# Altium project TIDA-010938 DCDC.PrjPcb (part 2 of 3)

## Sheet TIDA-010938 bidirectional DC-DC_Interleaved1.SchDoc
size 558 x 431 mm; Date: Not shown in title block; ApprovedBy: Not shown in title block; CheckedBy: Not shown in title block; Author: Not shown in title block; CompanyName: Not shown in title block; Engineer: Not shown in title block; Organization: Not shown in title block; Address1: Not shown in title block; Address2: Not shown in title block; Address3: Not shown in title block; Address4: Not shown in title block; DocumentNumber: 1; Revision: Use project parameter SCH_Rev; SheetNumber: 5; SheetTotal: 9; PageSetup: Record=PageOptions¦CenterHorizontal=True¦CenterVertical=True¦PrintScale=1.00¦XCorrection=1.00¦YCorrection=1.00¦PrintKind=0¦BorderSize=5000000¦LeftOffset=0¦BottomOffset=0¦Orientation=2¦PaperLength=1000¦PaperWidth=1000¦Scale=100¦PaperSource=15¦PrintQuality=600¦MediaType=1¦DitherType=10¦PaperKind=Letter¦PrintScaleMode=1
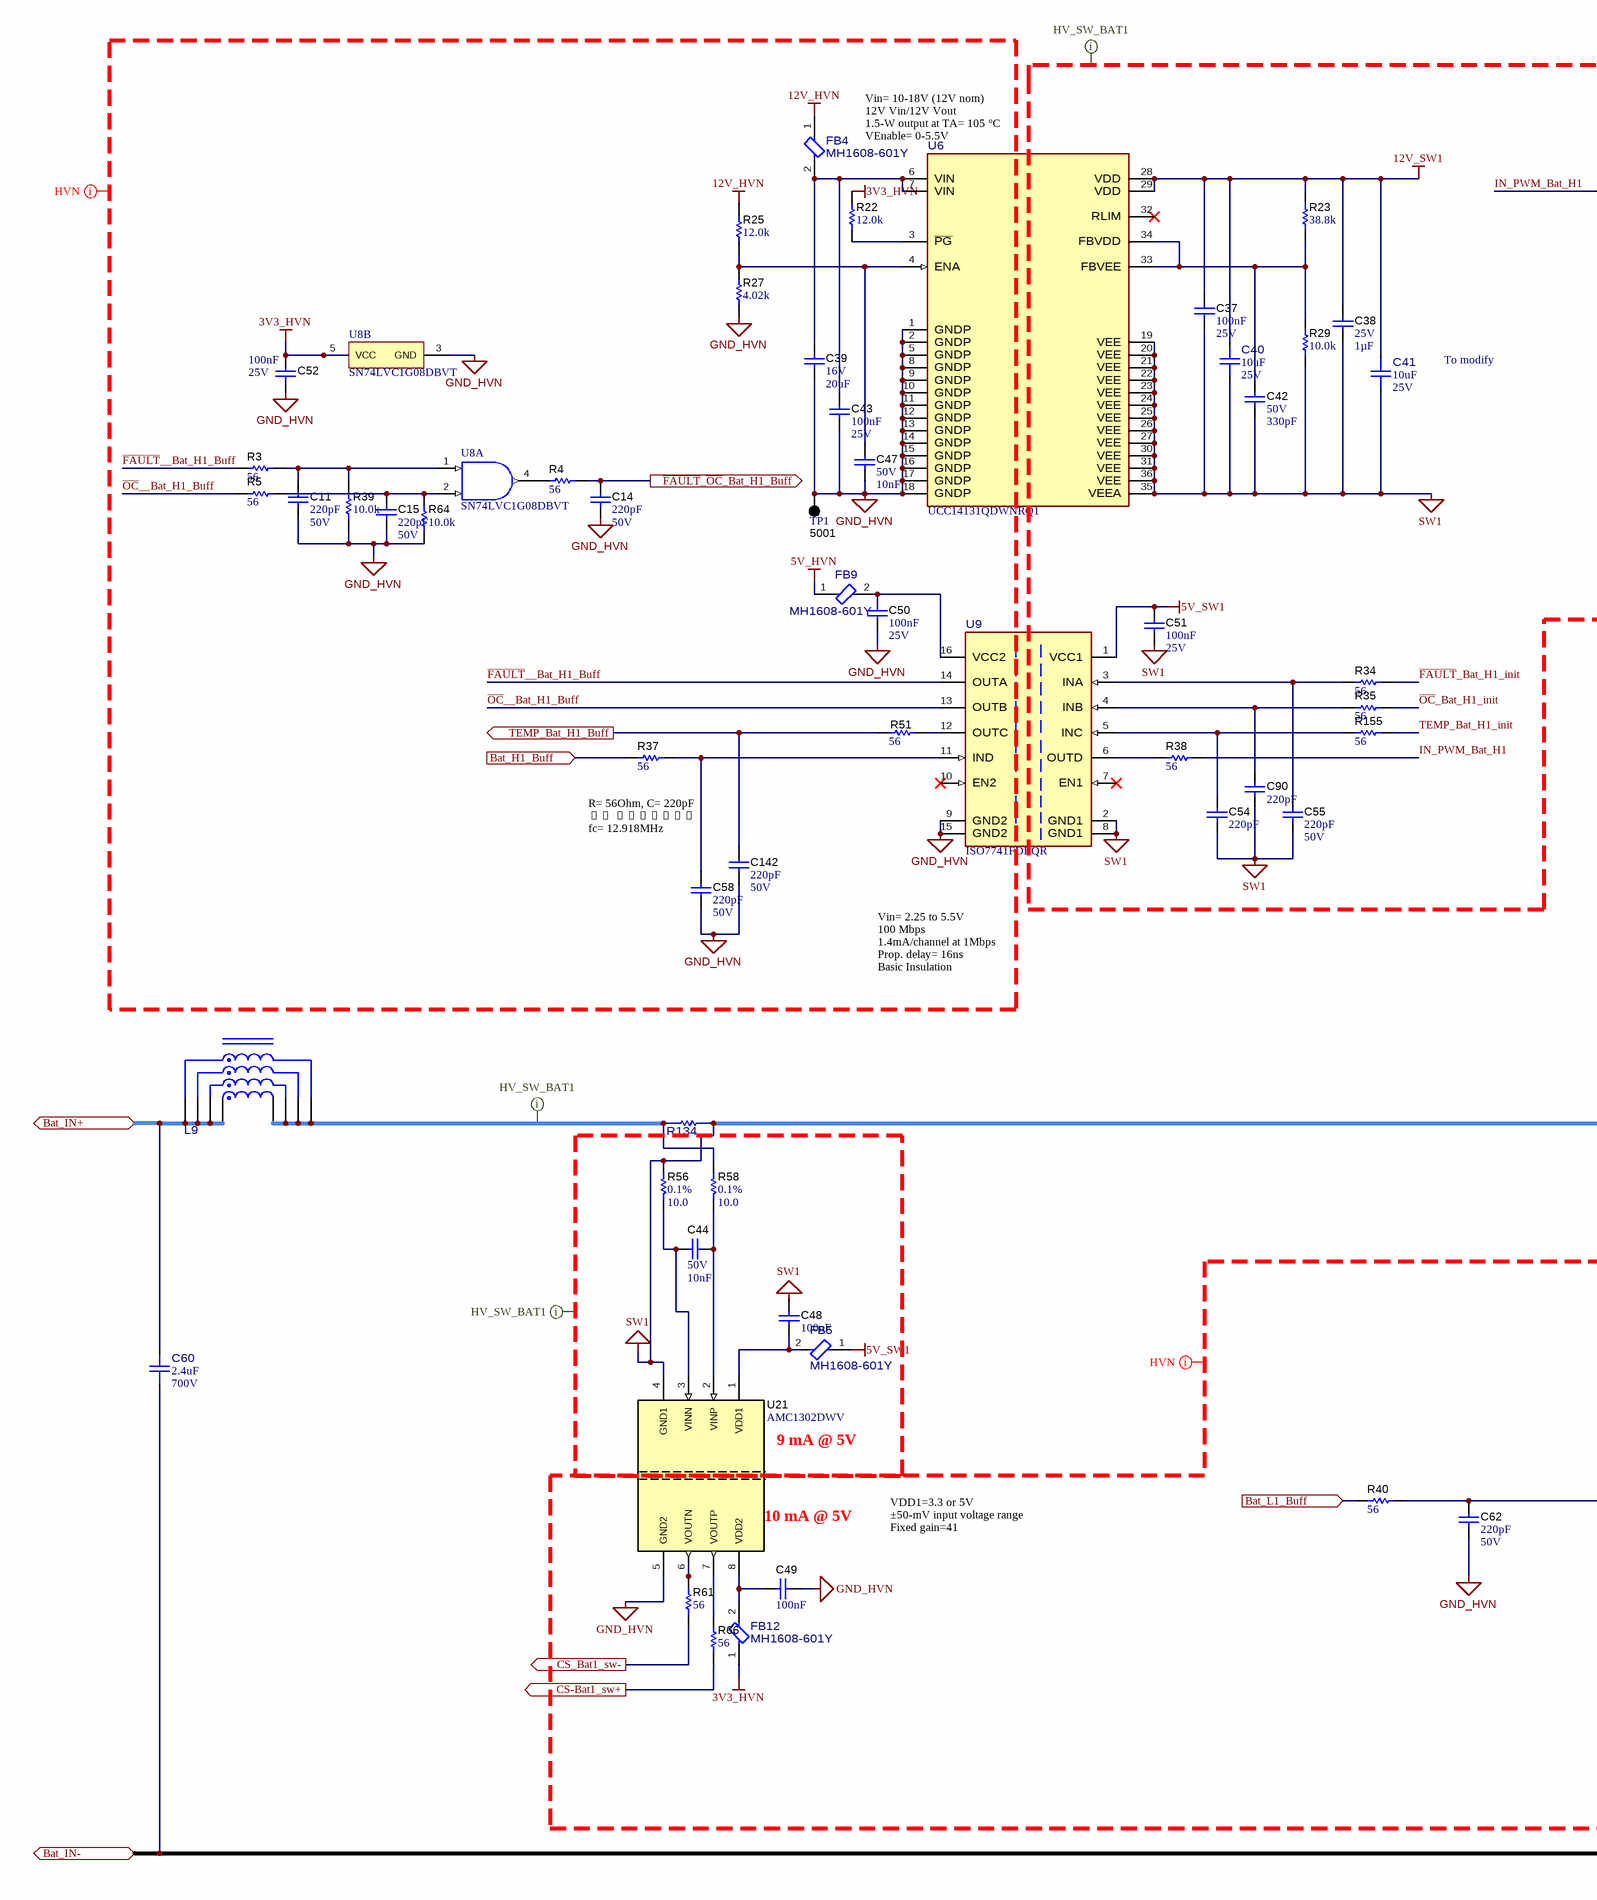
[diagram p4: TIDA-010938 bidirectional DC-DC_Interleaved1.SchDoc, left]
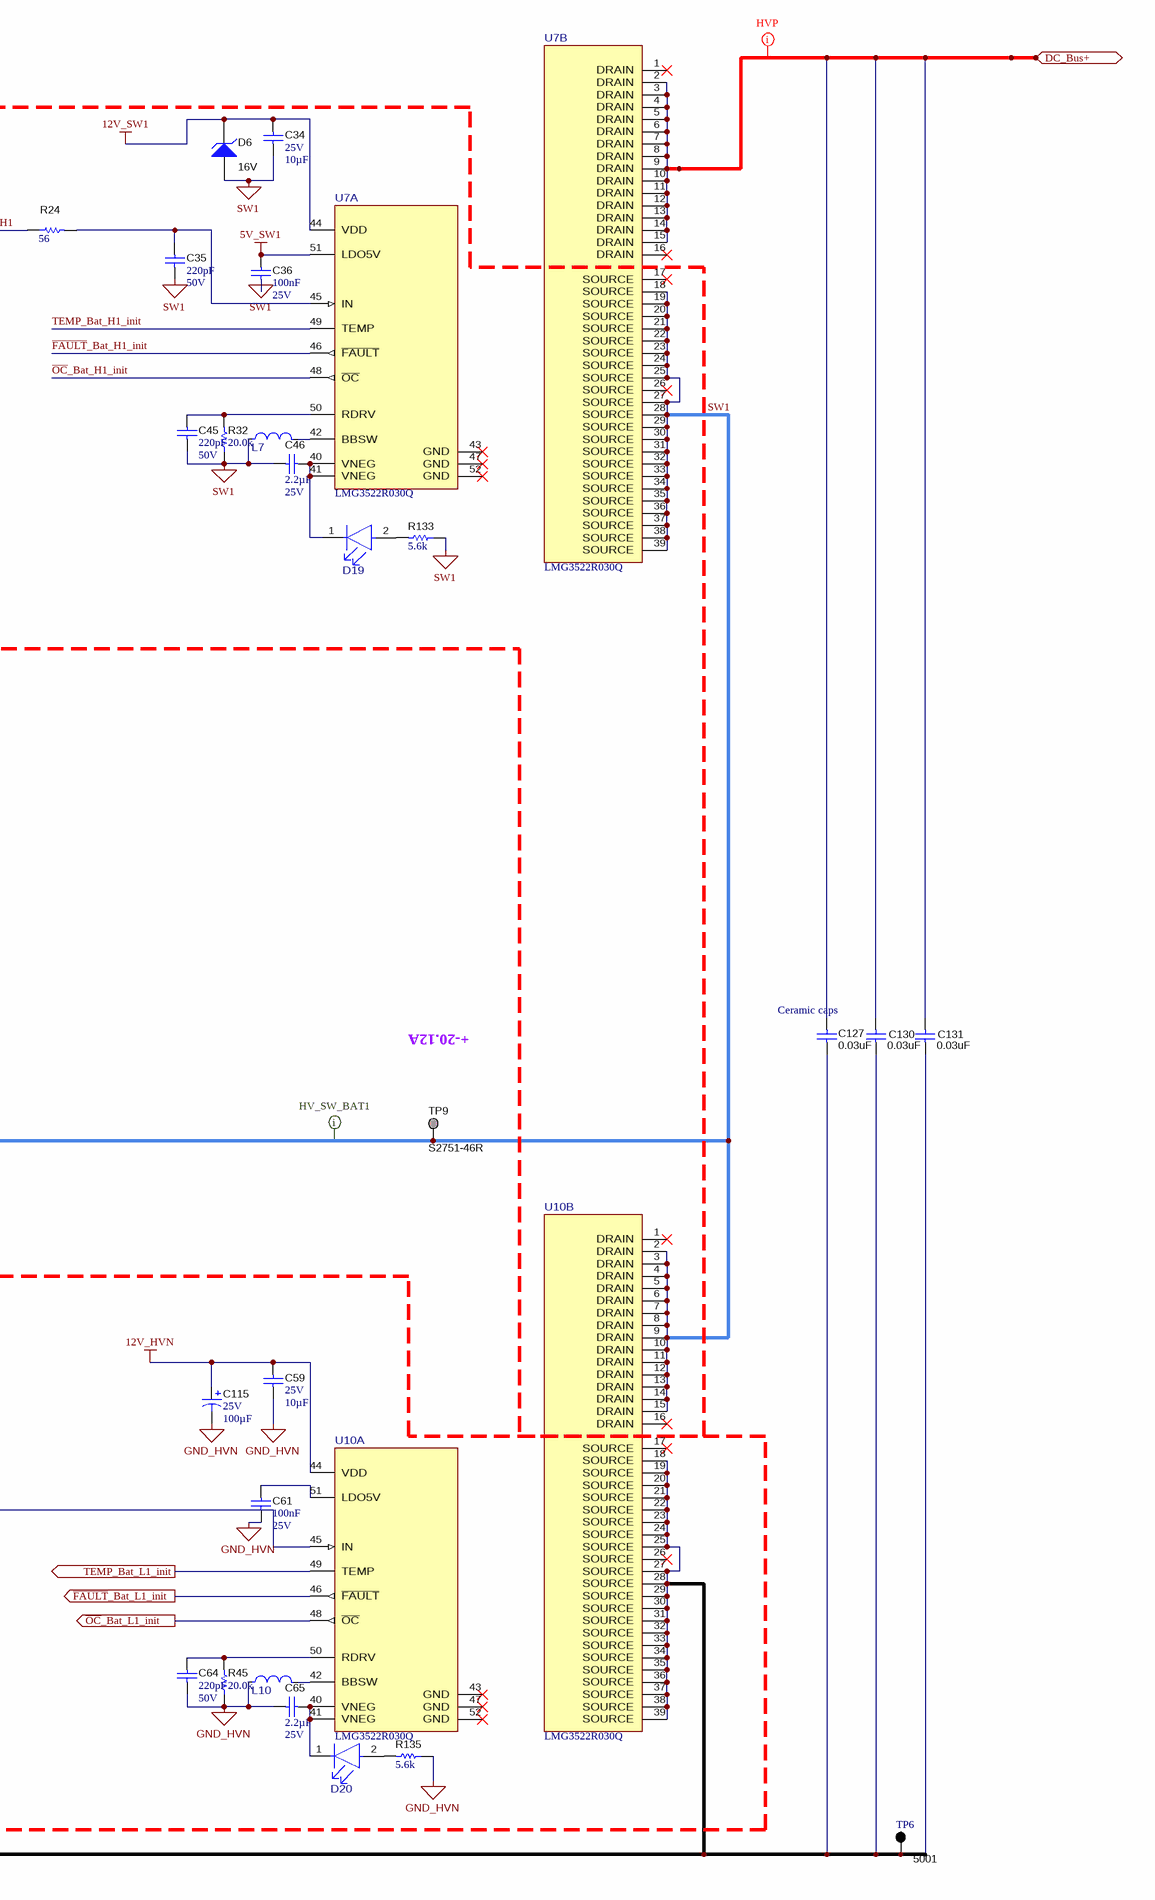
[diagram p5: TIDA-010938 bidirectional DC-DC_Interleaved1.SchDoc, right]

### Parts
C11  Cap_F: 220pF  VDC_V: 50V  [0603]  (hidden comment: GRM188R71H221KA01D)
C14  Cap_F: 220pF  VDC_V: 50V  [0603]  (hidden comment: GRM188R71H221KA01D)
C15  Cap_F: 220pF  VDC_V: 50V  [0603]  (hidden comment: GRM188R71H221KA01D)
C34  VDC_V: 25V  ValueDisplayed: 10µF  [1206_180]  (hidden comment: TMK316AB7106KLHT)
C35  Cap_F: 220pF  VDC_V: 50V  [0603]  (hidden comment: GRM188R71H221KA01D)
C36  Cap_F: 100nF  VDC_V: 25V  [0603]  (hidden comment: 06033C104JAT2A)
C37  Cap_F: 100nF  VDC_V: 25V  [0603]  (hidden comment: 06033C104JAT2A)
C38  VDC_V: 25V  ValueDisplayed: 1µF  [0603]  (hidden comment: TMK107BJ105KA-T)
C39  VDC_V: 16V  ValueDisplayed: 20uF  [0704]  (hidden comment: GRMJN7R61C206ME05)
C40  ValueDisplayed: 10uF  VDC_V: 25V  [FP-ZRB18AR61E106ME01L_0603-MFG]  (hidden comment: ZRB18AR61E106ME01L)
C41  ValueDisplayed: 10uF  VDC_V: 25V  [FP-ZRB18AR61E106ME01L_0603-MFG]  (hidden comment: ZRB18AR61E106ME01L)
C42  VDC_V: 50V  ValueDisplayed: 330pF  [0603]  (hidden comment: GRM1885C1H331JA01D)
C43  Cap_F: 100nF  VDC_V: 25V  [0603]  (hidden comment: 06033C104JAT2A)
C44  VDC_V: 50V  Cap_F: 10nF  [0603]  (hidden comment: 885012206089)
C45  Cap_F: 220pF  VDC_V: 50V  [0603]  (hidden comment: GRM188R71H221KA01D)
C46  Cap_F: 2.2µF  VDC_V: 25V  [0805_HV]  (hidden comment: CGA4J3X7R1E225K125AB)
C47  VDC_V: 50V  Cap_F: 10nF  [0603]  (hidden comment: 885012206089)
C48  Cap_F: 100nF  [0603]  (hidden comment: 06033C104JAT2A)
C49  Cap_F: 100nF  [0603]  (hidden comment: 06033C104JAT2A)
C50  Cap_F: 100nF  VDC_V: 25V  [0603]  (hidden comment: 06033C104JAT2A)
C51  Cap_F: 100nF  VDC_V: 25V  [0603]  (hidden comment: 06033C104JAT2A)
C52  Cap_F: 100nF  VDC_V: 25V  [0603]  (hidden comment: 06033C104JAT2A)
C54  Cap_F: 220pF  [0603]  (hidden comment: GRM188R71H221KA01D)
C55  Cap_F: 220pF  VDC_V: 50V  [0603]  (hidden comment: GRM188R71H221KA01D)
C58  Cap_F: 220pF  VDC_V: 50V  [0603]  (hidden comment: GRM188R71H221KA01D)
C59  VDC_V: 25V  ValueDisplayed: 10µF  [1206_180]  (hidden comment: TMK316AB7106KLHT)
C60  ValueDisplayed: 2.4uF  VDC_V: 700V  [FP-C4AUJBU4240M1WJ_RADIAL-MFG]  (hidden comment: C4AUJBU4240M1WJ)
C61  Cap_F: 100nF  VDC_V: 25V  [0603]  (hidden comment: 06033C104JAT2A)
C62  Cap_F: 220pF  VDC_V: 50V  [0603]  (hidden comment: GRM188R71H221KA01D)
C64  Cap_F: 220pF  VDC_V: 50V  [0603]  (hidden comment: GRM188R71H221KA01D)
C65  Cap_F: 2.2µF  VDC_V: 25V  [0805_HV]  (hidden comment: CGA4J3X7R1E225K125AB)
C90  Cap_F: 220pF  [0603]  (hidden comment: GRM188R71H221KA01D)
C115  VDC_V: 25V  ValueDisplayed: 100µF  [UWT_630x770]  (hidden comment: UWT1E101MCL1GS)
C127  ValueDisplayed: 0.03uF  [1812_254]  (hidden comment: C1812C303KDGLCAUTO)
C130  ValueDisplayed: 0.03uF  [1812_254]  (hidden comment: C1812C303KDGLCAUTO)
C131  ValueDisplayed: 0.03uF  [1812_254]  (hidden comment: C1812C303KDGLCAUTO)
C142  Cap_F: 220pF  VDC_V: 50V  [0603]  (hidden comment: GRM188R71H221KA01D)
D6  value 16V  [SOD-123]  (hidden comment: BZT52C16-7-F)
D19  KG DELLS1.22-JGKH-24  [FP-KG DELLS1.22-JGKH-24_0603-MFG]  (value not drawn)
D20  KG DELLS1.22-JGKH-24  [FP-KG DELLS1.22-JGKH-24_0603-MFG]  (value not drawn)
FB4  MH1608-601Y  [FP-MH1608-601Y_0603-MFG]
FB5  MH1608-601Y  [FP-MH1608-601Y_0603-MFG]
FB9  MH1608-601Y  [FP-MH1608-601Y_0603-MFG]
FB12  MH1608-601Y  [FP-MH1608-601Y_0603-MFG]
L7  SDEM20161T-4R7MS  [FP-SDEM20161T-4R7MS_SMD2-MFG]  (value not drawn)
L9  145452  [FP-145452_PTH_INDUCTOR_38MM5_60MM0-MFG]  (value not drawn)
L10  SDEM20161T-4R7MS  [FP-SDEM20161T-4R7MS_SMD2-MFG]  (value not drawn)
R3  ValueDisplayed: 56  [0603]  (hidden comment: RG1608P-560-B-T5)
R4  ValueDisplayed: 56  [0603]  (hidden comment: RG1608P-560-B-T5)
R5  ValueDisplayed: 56  [0603]  (hidden comment: RG1608P-560-B-T5)
R22  ValueDisplayed: 12.0k  [0603]  (hidden comment: ERJ-3EKF1202V)
R23  ValueDisplayed: 38.8k  [0603]  (hidden comment: RT0603DRE0738K8L)
R24  ValueDisplayed: 56  [0603]  (hidden comment: RG1608P-560-B-T5)
R25  ValueDisplayed: 12.0k  [0603]  (hidden comment: ERJ-3EKF1202V)
R27  ValueDisplayed: 4.02k  [0603]  (hidden comment: RT0603BRD074K02L)
R29  ValueDisplayed: 10.0k  [0603]  (hidden comment: RG1608P-103-B-T5)
R32  ValueDisplayed: 20.0k  [0603]  (hidden comment: RC0603FR-0720KL)
R34  ValueDisplayed: 56  [0603]  (hidden comment: RG1608P-560-B-T5)
R35  ValueDisplayed: 56  [0603]  (hidden comment: RG1608P-560-B-T5)
R37  ValueDisplayed: 56  [0603]  (hidden comment: RG1608P-560-B-T5)
R38  ValueDisplayed: 56  [0603]  (hidden comment: RG1608P-560-B-T5)
R39  ValueDisplayed: 10.0k  [0603]  (hidden comment: RG1608P-103-B-T5)
R40  ValueDisplayed: 56  [0603]  (hidden comment: RG1608P-560-B-T5)
R45  ValueDisplayed: 20.0k  [0603]  (hidden comment: RC0603FR-0720KL)
R51  ValueDisplayed: 56  [0603]  (hidden comment: RG1608P-560-B-T5)
R56  Tolerance_%: 0.1%  ValueDisplayed: 10.0  [0603]  (hidden comment: RT0603BRD0710RL)
R58  Tolerance_%: 0.1%  ValueDisplayed: 10.0  [0603]  (hidden comment: RT0603BRD0710RL)
R61  ValueDisplayed: 56  [0603]  (hidden comment: RG1608P-560-B-T5)
R64  ValueDisplayed: 10.0k  [0603]  (hidden comment: RG1608P-103-B-T5)
R66  ValueDisplayed: 56  [0603]  (hidden comment: RG1608P-560-B-T5)
R133  ValueDisplayed: 5.6k  [0603]  (hidden comment: RC0603JR-075K6L)
R134  CSS2H-2512K-1L50FE  [FP-CSS2H-2512K-1L80FE_2512-MFG]  (value not drawn)
R135  ValueDisplayed: 5.6k  [0603]  (hidden comment: RC0603JR-075K6L)
R155  ValueDisplayed: 56  [0603]  (hidden comment: RG1608P-560-B-T5)
TP1  5001  [Keystone5001]
TP6  5001  [Keystone5001]
TP9  S2751-46R  [Harwin_S2751-46R]  (no BOM)
U6  UCC14131QDWNRQ1  [DWJ0036A-MFG]
U7  LMG3522R030Q  [RQS0052C-C01-MFG]  (parts A,B of 2)
U8  SN74LVC1G08DBVT  [DBV0005A_N]  (parts A,B of 2)
U9  ISO7741FDBQR  [DBQ0016A-MFG]
U10  LMG3522R030Q  [RQS0052C-C01-MFG]  (parts A,B of 2)
U21  AMC1302DWV  [DWV0008A]

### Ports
Bat_H1_Buff (in), Bat_IN+ (bidir), Bat_IN- (bidir), Bat_L1_Buff (in), CS-Bat1_sw+ (out), CS_Bat1_sw- (out), DC_Bus+ (bidir), TEMP_Bat_H1_Buff (out), TEMP_Bat_L1_init (out), ~{FAULT}_Bat_L1_init (out), ~{FAULT}_~{OC}_Bat_H1_Buff (out), ~{OC}_Bat_L1_init (out)

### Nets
3V3_HVN: C52.1 FB12.1 R22.1 U8.5(VCC)
5V_HVN: FB9.1
5V_SW1: C36.2 C51.2 FB5.1 U7.51(LDO5V) U9.1(VCC1)
12V_HVN: C59.1 C115.1(+) FB4.1 R25.1 U10.44(VDD)
12V_SW1: C34.1 C37.2 C38.2 C40.1 C41.1 D6.1(K) R23.1 U6.28(VDD) U6.29(VDD) U7.44(VDD)
GND_HVN: C11.1 C14.1 C15.1 C39.1 C43.1 C47.1 C49.2 C50.1 C52.2 C58.1 C59.2 C60.1 C61.1 C62.1 C64.1 C65.2 C115.2(-) C127.2 C130.2 C131.2 C142.1 L10.1 R27.1 R39.1 R45.1 R64.1 R135.1 TP1.1 TP6.1 U6.1(GNDP) U6.2(GNDP) U6.5(GNDP) U6.8(GNDP) U6.9(GNDP) U6.10(GNDP) U6.11(GNDP) U6.12(GNDP) U6.13(GNDP) U6.14(GNDP) U6.15(GNDP) U6.16(GNDP) U6.17(GNDP) U6.18(GNDP) U8.3(GND) U9.9(GND2) U9.15(GND2) U10.18(SOURCE) U10.19(SOURCE) U10.20(SOURCE) U10.21(SOURCE) U10.22(SOURCE) U10.23(SOURCE) U10.24(SOURCE) U10.25(SOURCE) U10.27(SOURCE) U10.28(SOURCE) U10.29(SOURCE) U10.30(SOURCE) U10.31(SOURCE) U10.32(SOURCE) U10.33(SOURCE) U10.34(SOURCE) U10.35(SOURCE) U10.36(SOURCE) U10.37(SOURCE) U10.38(SOURCE) U10.39(SOURCE) U21.5(GND2) ; port Bat_IN-  [project net DC_Bus-]
SW1: C34.2 C35.1 C36.1 C37.1 C38.1 C40.2 C41.2 C42.2 C45.1 C46.2 C48.2 C51.1 C54.1 C55.1 C90.1 D6.2(A) L7.1 R29.2 R32.1 R56.1 R133.1 R134.2 TP9.1 U6.19(VEE) U6.20(VEE) U6.21(VEE) U6.22(VEE) U6.23(VEE) U6.24(VEE) U6.25(VEE) U6.26(VEE) U6.27(VEE) U6.30(VEE) U6.31(VEE) U6.35(VEEA) U6.36(VEE) U7.18(SOURCE) U7.19(SOURCE) U7.20(SOURCE) U7.21(SOURCE) U7.22(SOURCE) U7.23(SOURCE) U7.24(SOURCE) U7.25(SOURCE) U7.27(SOURCE) U7.28(SOURCE) U7.29(SOURCE) U7.30(SOURCE) U7.31(SOURCE) U7.32(SOURCE) U7.33(SOURCE) U7.34(SOURCE) U7.35(SOURCE) U7.36(SOURCE) U7.37(SOURCE) U7.38(SOURCE) U7.39(SOURCE) U9.2(GND1) U9.8(GND1) U10.2(DRAIN) U10.3(DRAIN) U10.4(DRAIN) U10.5(DRAIN) U10.6(DRAIN) U10.7(DRAIN) U10.8(DRAIN) U10.9(DRAIN) U10.10(DRAIN) U10.11(DRAIN) U10.12(DRAIN) U10.13(DRAIN) U10.14(DRAIN) U10.15(DRAIN) U21.4(GND1)
Bat_H1_Buff: R37.1 ; port Bat_H1_Buff
Bat_IN+: C60.2 L9.1 L9.2 L9.3 L9.4 ; port Bat_IN+
Bat_L1_Buff: R40.1 ; port Bat_L1_Buff
CS-Bat1_sw+: R66.1 ; port CS-Bat1_sw+
CS_Bat1_sw-: R61.1 ; port CS_Bat1_sw-
DC_Bus+: C127.1 C130.1 C131.1 U7.2(DRAIN) U7.3(DRAIN) U7.4(DRAIN) U7.5(DRAIN) U7.6(DRAIN) U7.7(DRAIN) U7.8(DRAIN) U7.9(DRAIN) U7.10(DRAIN) U7.11(DRAIN) U7.12(DRAIN) U7.13(DRAIN) U7.14(DRAIN) U7.15(DRAIN) ; port DC_Bus+
~{FAULT}__Bat_H1_Buff: R3.1 U9.14(OUTA)
~{FAULT}_Bat_H1_init: R34.2 U7.46(~{FAULT})
~{FAULT}_Bat_L1_init: U10.46(~{FAULT}) ; port ~{FAULT}_Bat_L1_init
~{FAULT}_~{OC}_Bat_H1_Buff: C14.2 R4.2 ; port ~{FAULT}_~{OC}_Bat_H1_Buff
IN_PWM_Bat_H1: R24.1 R38.2
~{OC}__Bat_H1_Buff: R5.1 U9.13(OUTB)
~{OC}_Bat_H1_init: R35.2 U7.48(~{OC})
~{OC}_Bat_L1_init: U10.48(~{OC}) ; port ~{OC}_Bat_L1_init
TEMP_Bat_H1_Buff: C142.2 R51.1 ; port TEMP_Bat_H1_Buff
TEMP_Bat_H1_init: R155.2 U7.49(TEMP)
TEMP_Bat_L1_init: U10.49(TEMP) ; port TEMP_Bat_L1_init
NetC11_2: C11.2 R3.2 R39.2 U8.1(A)
NetC15_2: C15.2 R5.2 R64.2 U8.2(B)
NetC35_2: C35.2 R24.2 U7.45(IN)
NetC39_2: C39.2 C43.2 FB4.2 U6.6(VIN) U6.7(VIN)
NetC42_1: C42.1 R23.2 R29.1 U6.33(FBVEE) U6.34(FBVDD)
NetC44_1: C44.1 R58.2 U21.2(VINP)
NetC44_2: C44.2 R56.2 U21.3(VINN)
NetC45_2: C45.2 R32.2 U7.50(RDRV)
NetC46_1: C46.1 D19.1(CATHODE) U7.40(VNEG) U7.41(VNEG)
NetC47_2: C47.2 R25.2 R27.2 U6.4(ENA)
NetC48_1: C48.1 FB5.2 U21.1(VDD1)
NetC49_1: C49.1 FB12.2 U21.8(VDD2)
NetC50_2: C50.2 FB9.2 U9.16(VCC2)
NetC54_2: C54.2 R155.1 U9.5(INC)
NetC55_2: C55.2 R34.1 U9.3(INA)
NetC58_2: C58.2 R37.2 U9.11(IND)
NetC61_2: C61.2 U10.51(LDO5V)
NetC62_2: C62.2 R40.2 U10.45(IN)
NetC64_2: C64.2 R45.2 U10.50(RDRV)
NetC65_1: C65.1 D20.1(CATHODE) U10.40(VNEG) U10.41(VNEG)
NetC90_2: C90.2 R35.1 U9.4(INB)
NetD19_2: D19.2(ANODE) R133.2
NetD20_2: D20.2(ANODE) R135.2
NetL7_2: L7.2 U7.42(BBSW)
NetL9_5: L9.5 L9.6 L9.7 L9.8 R58.1 R134.1
NetL10_2: L10.2 U10.42(BBSW)
NetR4_1: R4.1 U8.4(Y)
NetR22_2: R22.2 U6.3(~{PG})
NetR38_1: R38.1 U9.6(OUTD)
NetR51_2: R51.2 U9.12(OUTC)
NetR61_2: R61.2 U21.6(VOUTN)
NetR66_2: R66.2 U21.7(VOUTP)

Not connected (* = marked no-connect by the designer): U6 32(RLIM)*; U7 1(DRAIN)* 16(DRAIN)* 17(SOURCE)* 26(SOURCE)* 43(GND)* 47(GND)* 52(GND)*; U9 7(EN1)* 10(EN2)*; U10 1(DRAIN)* 16(DRAIN)* 17(SOURCE)* 26(SOURCE)* 43(GND)* 47(GND)* 52(GND)*

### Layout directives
net class HVN: 3V3_HVN, 5V_HVN, 5V_SW1, 12V_HVN, 12V_SW1, GND_HVN, IN_PWM_Bat_H1, SW1, TEMP_Bat_H1_init, ~{FAULT}__Bat_H1_Buff, ~{FAULT}_Bat_H1_init, ~{OC}__Bat_H1_Buff, ~{OC}_Bat_H1_init
net class HV_SW_BAT1: 3V3_HVN, 5V_SW1, 12V_HVN, 12V_SW1, GND_HVN, IN_PWM_Bat_H1, NetL9_5, SW1, TEMP_Bat_H1_init, ~{FAULT}_Bat_H1_init, ~{OC}_Bat_H1_init
net class HVP: DC_Bus+

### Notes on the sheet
- Vin= 10-18V (12V nom)
  12V Vin/12V Vout
  1.5-W output at TA= 105 °C
  VEnable= 0-5.5V
- To modify
- R= 56Ohm, C= 220pF
  𝜏= 1.23e-8
  fc= 12.918MHz
- Vin= 2.25 to 5.5V
  100 Mbps
  1.4mA/channel at 1Mbps
  Prop. delay= 16ns
  Basic Insulation
- +-20.12A
- (near C127) Ceramic caps
- (near U21) 9 mA @ 5V
- (near U21) 10 mA @ 5V
- VDD1=3.3 or 5V
  ±50-mV input voltage range
  Fixed gain=41

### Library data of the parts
C11 C14 C15 C35 C45 C55 C58 C62 C64 C142 = CMP-0007442-5: CAP, CERM, 220 pF, 50 V, +/- 10%, X7R, 0603; Manufacturer: MuRata; TaMin_C: -55°C; Polarized: N; SizeAreaWB_mm2: 4.68; Value1: Unknown; U/M: EA; Value: 220pF; TaMax_C: 125°C; SizeZ_mm: 1; SizeX_mm: 1.6; SizeY_mm: 0.8; SizeArea_mm2: 1.28; AEC Category: Q200
C34 C59 = CMP-0750154-1: CAP, CERM, 10 µF, 25 V,+/- 10%, X7R, AEC-Q200 Grade 1, 1206; Manufacturer: Taiyo Yuden; AEC Qualified: Y; SizeZ_mm: 1.8; TaMax_C: 125°C; TaMin_C: -55°C; Cap_Case: 1206; Polarized: N; AEC Grade: 1; SizeY_mm: 1.6; Value: 10uF; SizeX_mm: 3.2; SizeAreaWB_mm2: 10.92; AEC Category: Q200; U/M: EA; SizeArea_mm2: 5.12
C36 C37 C43 C50-C52 C61 = CMP-0006752-5: CAP, CERM, 0.1 uF, 25 V, +/- 5%, X7R, 0603; Manufacturer: AVX; TaMin_C: -55°C; ESR_ohm: 0.05; Polarized: N; SizeAreaWB_mm2: 4.68; Value1: 0.05 ohm; U/M: EA; Value: 0.1uF; TaMax_C: 125°C; SizeZ_mm: 1; SizeX_mm: 1.6; SizeY_mm: 0.8; SizeArea_mm2: 1.28; AEC Category: Q200
C38 = CMP-0086152-1: CAP, CERM, 1 µF, 25 V,+/- 10%, X5R, 0603; Manufacturer: Taiyo Yuden; SizeAreaWB_mm2: 4.68; SizeZ_mm: 1; U/M: EA; Green_REACh: Passed; Value: 1uF; AEC Qualified: N; TaMax_C: 85°C; Green_Lifecycle: Active; AEC Category: Q200; SizeArea_mm2: 1.28; TaMin_C: -55°C; SizeY_mm: 0.8; SizeX_mm: 1.6
C39 = CMP-0009474-2: CAP, CERM, 20 uF, 16 V, +/- 20%, X5R, 0704; Manufacturer: MuRata; TaMin_C: -55°C; Polarized: N; SizeAreaWB_mm2: 5.6; Value1: Unknown; U/M: EA; Value: 20uF; TaMax_C: 85°C; SizeZ_mm: 0.8; SizeX_mm: 1; SizeY_mm: 1.8; Cap_F: 20µF; AEC Category: Q200
C40 C41 = CMP-0094458-1: 10µF ±20% 25V Ceramic Capacitor X5R 0603 (1608 Metric); Manufacturer: Murata Electronics; SizeZ_mm: 1.2mm; AEC Qualified: No
C42 = CMP-0007209-4: CAP, CERM, 330 pF, 50 V, +/- 5%, C0G/NP0, 0603; Manufacturer: MuRata; TaMin_C: -55°C; Polarized: N; SizeAreaWB_mm2: 4.68; Value1: Unknown; U/M: EA; Value: 330pF; TaMax_C: 125°C; SizeZ_mm: 1; SizeX_mm: 1.6; SizeY_mm: 0.8; SizeArea_mm2: 1.28; AEC Category: Q200
C44 C47 = CMP-0750039-1: CAP, CERM, 0.01 µF, 50 V,+/- 10%, X7R, 0603; Manufacturer: Wurth Elektronik; Polarized: N; AEC Category: Q200; TaMax_C: 125°C; SizeAreaWB_mm2: 4.68; Value: 0.01uF; SizeArea_mm2: 1.28; SizeY_mm: 0.8; SizeZ_mm: 1; ValueDisplayed: 0.01µF; SizeX_mm: 1.6; U/M: EA; TaMin_C: -55°C
C46 C65 = CMP-0007975-2: CAP, CERM, 2.2 uF, 25 V, +/- 10%, X7R, AEC-Q200 Grade 1, 0805; Manufacturer: TDK; TaMin_C: -55°C; Polarized: N; SizeAreaWB_mm2: 6.75; Value1: Unknown; U/M: EA; Value: 2.2uF; TaMax_C: 125°C; SizeZ_mm: 1.45; SizeX_mm: 2; SizeY_mm: 1.25; Cap_Case: 0805; SizeArea_mm2: 2.5; AEC Qualified: Y; AEC Grade: 1; AEC Category: Q200
C48 C49 = CMP-0006752-5: CAP, CERM, 0.1 uF, 25 V, +/- 5%, X7R, 0603; Manufacturer: AVX; TaMin_C: -55°C; ESR_ohm: 0.05; Polarized: N; SizeAreaWB_mm2: 4.68; Value1: 0.05 ohm; U/M: EA; Value: 0.1uF; TaMax_C: 125°C; SizeZ_mm: 1; SizeX_mm: 1.6; SizeY_mm: 0.8; Value2: 25V; SizeArea_mm2: 1.28; AEC Category: Q200
C54 C90 = CMP-0007442-5: CAP, CERM, 220 pF, 50 V, +/- 10%, X7R, 0603; Manufacturer: MuRata; TaMin_C: -55°C; Polarized: N; SizeAreaWB_mm2: 4.68; Value1: Unknown; U/M: EA; Value: 220pF; TaMax_C: 125°C; SizeZ_mm: 1; SizeX_mm: 1.6; SizeY_mm: 0.8; Value2: 50V; SizeArea_mm2: 1.28; AEC Category: Q200
C60 = CMP-0045063-1: 2.4 µF Film Capacitor 700V Polypropylene (PP), Metallized Radial; Manufacturer: KEMET; AEC Grade: Grade 2; AEC Qualified: Yes; Cap_F: 2.4µF; SizeZ_mm: 20.7mm; Tolerance_%: 5%; Value: 2.4µF
C115 = CMP-0081462-1: CAP, AL, 100 µF, 25 V, +/- 20%, SMD; Manufacturer: Nichicon; TaMin_C: -55°C; Polarized: Y; SizeAreaWB_mm2: 77.4; U/M: EA; Value: 100uF; TaMax_C: 105°C; SizeZ_mm: 8; SizeX_mm: 7; SizeY_mm: 6.6; Cap_Case: 6.3x7.7mm; SizeArea_mm2: 46.2; CompType: Capacitor; AEC Qualified: N; IRMS_A: 91mA; AEC Category: Q200
C127 C130 C131 = CMP-0009326-2: 0.03 µF ±10% 1000V (1kV) Ceramic Capacitor C0G, NP0 1812 (4532 Metric); Manufacturer: Kemet; Polarized: N; Value: 0.03uF; U/M: EA; Cap_F: 30nF; Value1: Unknown; TaMin_C: -55°C; TaMax_C: 125°C; Cap_Case: 1812; AEC Category: Q200; SizeArea_mm2: 14.4; SizeAreaWB_mm2: 23.1; SizeX_mm: 4.5; SizeY_mm: 3.2; SizeZ_mm: 2.54
D6 = CMP-0005769-4: Diode, Zener, 16 V, 500 mW, AEC-Q101, SOD-123; Manufacturer: Diodes Inc.; SizeZ_mm: 1.35; AEC Qualified: Y; SizeX_mm: 3.85; AEC Category: Q101; Power_W: 500mW; SizeY_mm: 1.7; Value1: 0.5W; SizeAreaWB_mm2: 13.095; SizeArea_mm2: 6.545; RJA_CperW: 338
D19 D20 = CMP-0093310-1: Standard LEDs - SMD Green TOPLED E 1608; Manufacturer: Osram Opto; AEC Grade: Grade 2; LambdaP: 572nm; SizeZ_mm: 0.7mm; LuminousFlux_PhiV: 0.016-0.0295lm; Luminous Intensity: 4.5-9.7mcd; LambdaD: 570nm; Tjmax_C: 125°C; Angle: 120°; Led Orientation: Top View; Forward Current: 2mA; Vf_V: 1.8V; AEC Qualified: Yes; Vr_V: 12V
FB4 FB5 FB9 FB12 = CMP-0037505-1: 600 Ohms @ 100 MHz 1 Power, Signal Line Ferrite Bead 0603 (1608 Metric) 1A 200mOhm; Manufacturer: Bourns; DCR_ohm: 0.2; SizeZ_mm: 1mm; AEC Qualified: No; Impedance At Frequency: 600Ω @ 100MHz; Test Frequency: 100MHz; Tolerance_%: 25%
L7 L10 = CMP-0089347-1: 4.7µH Unshielded Inductor 1.1A 426mOhm Max 0806 (2016 Metric); Manufacturer: Cyntec; AEC Qualified: No; Material: Metal Dust; Isat: 1.26A; Test Frequency: 1MHz; DCR_ohm: 0.426; SizeZ_mm: 1mm; Tolerance_%: 20%
L9 = CMP-0123019-1: Inductor; Manufacturer: Bourns; AEC Qualified: No; DCR_ohm: 23m; Ind_H: 186µH; Isat: 23.5A; SizeZ_mm: 42mm; Value: 200uH; Test Frequency: 100kHz; Tolerance_%: 10%
R3-R5 R24 R34 R35 R37 R38 R40 R51 R61 R66 R155 = CMP-0023572-3: RES, 56, 0.1%, 0.1 W, 0603; Manufacturer: Susumu Co Ltd; Power_W: 100mW; TempCo: 25 ppm/C; Value_Code: 56R0; U/M: EA; Value: 56; SizeX_mm: 1.6; SizeY_mm: 0.8; SizeZ_mm: 1; Value2: 0.1W; SizeArea_mm2: 1.28; VDC_V: 75V; AEC Category: Q200
R22 R25 = CMP-0022685-3: RES, 12.0 k, 1%, 0.1 W, 0603; Manufacturer: Panasonic; Power_W: 100mW; TempCo: 100 ppm/C; Value_Code: 12k0; U/M: EA; Value: 12.0k; Res_ohm: 12k; SizeX_mm: 1.6; SizeY_mm: 0.8; SizeZ_mm: 1; Value2: 0.1W; SizeArea_mm2: 1.28; VDC_V: 75V; AEC Category: Q200
R23 = CMP-0025200-2: RES, 38.8 k, 0.5%, 0.1 W, 0603; Manufacturer: Yageo America; Power_W: 100mW; TempCo: 50 ppm/C; Value_Code: 38k8; U/M: EA; Value: 38.8k; EIA_Code: E192; SizeX_mm: 1.6; SizeY_mm: 0.8; SizeZ_mm: 1; Value2: 0.1W; SizeArea_mm2: 1.28; VDC_V: 75V; AEC Category: Q200
R27 = CMP-0024286-2: RES, 4.02 k, 0.1%, 0.1 W, 0603; Manufacturer: Yageo America; Power_W: 100mW; TempCo: 25 ppm/C; Value_Code: 4k02; U/M: EA; Value: 4.02k; EIA_Code: E192; SizeX_mm: 1.6; SizeY_mm: 0.8; SizeZ_mm: 1; Value2: 0.1W; SizeArea_mm2: 1.28; VDC_V: 75V; AEC Category: Q200
R29 = CMP-0023404-1: RES, 10.0 k, 0.1%, 0.1 W, 0603; Manufacturer: Susumu Co Ltd; Power_W: 100mW; TempCo: 25 ppm/C; Value_Code: 10k0; U/M: EA; Value: 10.0k; EIA_Code: E192; Res_ohm: 10k; SizeX_mm: 1.6; SizeY_mm: 0.8; SizeZ_mm: 1; Value2: 0.1W; SizeArea_mm2: 1.28; VDC_V: 75V; AEC Category: Q200
R32 R45 = CMP-0022906-5: RES, 20.0 k, 1%, 0.1 W, 0603; Manufacturer: Yageo; Power_W: 100mW; TempCo: 100 ppm/C; Value_Code: 20k0; Value: 20.0k; EIA_Code: E96; Res_ohm: 20k; SizeX_mm: 1.6; SizeY_mm: 0.8; SizeZ_mm: 1; Value2: 0.1W; SizeArea_mm2: 1.28; AEC Qualified: N; VDC_V: 75V; AEC Category: Q200; SizeAreaWB_mm2: 4.68
R39 R64 = CMP-0023404-3: RES, 10.0 k, 0.1%, 0.1 W, 0603; Manufacturer: Susumu Co Ltd; Power_W: 100mW; TempCo: 25 ppm/C; Value_Code: 10k0; U/M: EA; Value: 10.0k; EIA_Code: E192; Res_ohm: 10k; SizeX_mm: 1.6; SizeY_mm: 0.8; SizeZ_mm: 1; Value2: 0.1W; SizeArea_mm2: 1.28; VDC_V: 75V; AEC Category: Q200
R56 R58 = CMP-0023661-3: RES, 10.0, 0.1%, 0.1 W, 0603; Manufacturer: Yageo America; Power_W: 100mW; TempCo: 25 ppm/C; Value_Code: 10R0; U/M: EA; Value: 10.0; EIA_Code: E192; Res_ohm: 10; SizeX_mm: 1.6; SizeY_mm: 0.8; SizeZ_mm: 1; Value2: 0.1W; SizeArea_mm2: 1.28; VDC_V: 75V; AEC Category: Q200
R133 R135 = CMP-0025933-5: RES, 5.6 k, 5%, 0.1 W, 0603; Manufacturer: Yageo; Power_W: 100mW; TempCo: 100 ppm/C; Value_Code: 5k60; Value: 5.6k; EIA_Code: E24; SizeX_mm: 1.6; SizeY_mm: 0.8; SizeZ_mm: 1; Value2: 0.1W; SizeArea_mm2: 1.28; AEC Qualified: N; VDC_V: 75V; AEC Category: Q200; SizeAreaWB_mm2: 4.68
R134 = CMP-0123595-1: 1.5mOhms ±1% 3W Chip Resistor 2512 (6432 Metric) Automotive AEC-Q200, Current Sense Metal Element; Manufacturer: Bourns; PartNumber: CSS2H-2512K-1L80FE; AEC Grade: Grade 0; AEC Qualified: Yes; Power_W: 5W; Res_ohm: 1.5m; SizeZ_mm: 1.21mm; TempCo: 75ppm/°C; Value: 1.5m
TP1 TP6 = CMP-0055138-2: Test Point, Miniature, Black, TH; Manufacturer: Keystone Electronics; ContactFinish: Silver; CNHeader: FALSE; Green_Lifecycle: Active; Green_REACh: Passed; CT: TRUE
TP9 = CMP-0003968-1: Test Point, SMT; Manufacturer: Harwin
U6 = CMP-0033793-2: Automotive 1.5-W, 12-V VIN / 12-VOUT, 15-V VIN / 15-V VOUT, HighDensity, > 5-kVRMS, Isolated DC/DC Module; Manufacturer: Texas Instruments; SizeZ_mm: 3.55mm; AEC Qualified: Yes; AEC Grade: Grade 1; Max Supply Voltage: 18V; Min Supply Voltage: 9V; Nominal Supply Current: 200-270mA; Number Of Outputs: 2; Output Type: AdjustableProgrammable; Output Voltage: 10-18V; Standoff Height: 0.1mm; Switching Frequency: 18MHz; TaMax_C: +125°C; TaMin_C: -40°C; TJmax_C: +150°C; AEC Category: Q200; CompType: IC
U7 U10 = CMP-0089967-3: 650-V 30-mΩ GaN FET with Integrated Driver and Protection; Manufacturer: Texas Instruments; Standoff Height: 0mm; TJmax_C: +125°C; AEC Qualified: Yes; Nominal Supply Current: 16mA; Min Supply Voltage: 7.5V; SizeZ_mm: 1mm; AEC Category: Q200; Output Voltage: 520V; CompType: IC; Number Of Outputs: 1; Max Supply Voltage: 18V; AEC Grade: Grade 1
U8 = CMP-0051571-2: Single 2-Input Positive-AND Gate, DBV0005A, SMALL T&R; Manufacturer: Texas Instruments; Voltage(Nom)(V): 1.8,2.5,3.3,5; Bits(#): 1; Rating: Catalog; F @ Nom Voltage(Max)(Mhz): 150; 3-State Output: No; Gate Type: AND; Output Drive (IOL/IOH)(Max)(mA): 32/-32; Technology Family: LVC; Logic: True; VCC(Max)(V): 5.5; ICC @ Nom Voltage(Max)(mA): 0.01; VCC(Min)(V): 1.65; tpd @ Nom Voltage(Max)(ns): 4.5,6,4,5; Input Type: CMOS/TTL; Output Type: CMOS; AEC Category: Q200; AEC Qualified: N; CompType: IC
U9 = CMP-0089510-1: General Purpose Digital Isolator 5000Vrms 4 Channel 100Mbps 85kV/µs CMTI 16-SSOP (0.154", 3.90mm Width); Manufacturer: Texas Instruments; Nominal Supply Current: 0.8-18mA; SizeZ_mm: 1.75mm; TJmax_C: +150°C; TaMax_C: +125°C; Min Supply Voltage: 2.25V; TaMin_C: -55°C; AEC Qualified: No; Standoff Height: 0.11mm; Max Supply Voltage: 5.5V
U21 = CMP-0080671-1: Precision Reinforced Isolated Amplifier for Current Sensing, DWV0008A (SOIC-8); Alternate PartNumber: AMC1302DWVR; Alternate Manufacturer: Texas Instruments; SizeAreaWB_mm2: 105.975; SizeZ_mm: 2.8; SizeX_mm: 11.5; SizeY_mm: 5.85; SizeArea_mm2: 67.275; CompType: IC; AEC Qualified: N; AEC Category: Q200

## Sheet TIDA-010938 DC-DC_VoltageMeasurement.SchDoc
size 431 x 279 mm; Date: Not shown in title block; ApprovedBy: Not shown in title block; CheckedBy: Not shown in title block; Author: Not shown in title block; CompanyName: Not shown in title block; Engineer: Not shown in title block; Organization: Not shown in title block; Address1: Not shown in title block; Address2: Not shown in title block; Address3: Not shown in title block; Address4: Not shown in title block; DocumentNumber: 1; Revision: Use project parameter SCH_Rev; SheetNumber: 8; SheetTotal: 9; PageSetup: Record=PageOptions¦CenterHorizontal=True¦CenterVertical=True¦PrintScale=1.00¦XCorrection=1.00¦YCorrection=1.00¦PrintKind=0¦BorderSize=5000000¦LeftOffset=0¦BottomOffset=0¦Orientation=2¦PaperLength=1000¦PaperWidth=1000¦Scale=100¦PaperSource=15¦PrintQuality=600¦MediaType=1¦DitherType=10¦PaperKind=Letter¦PrintScaleMode=1
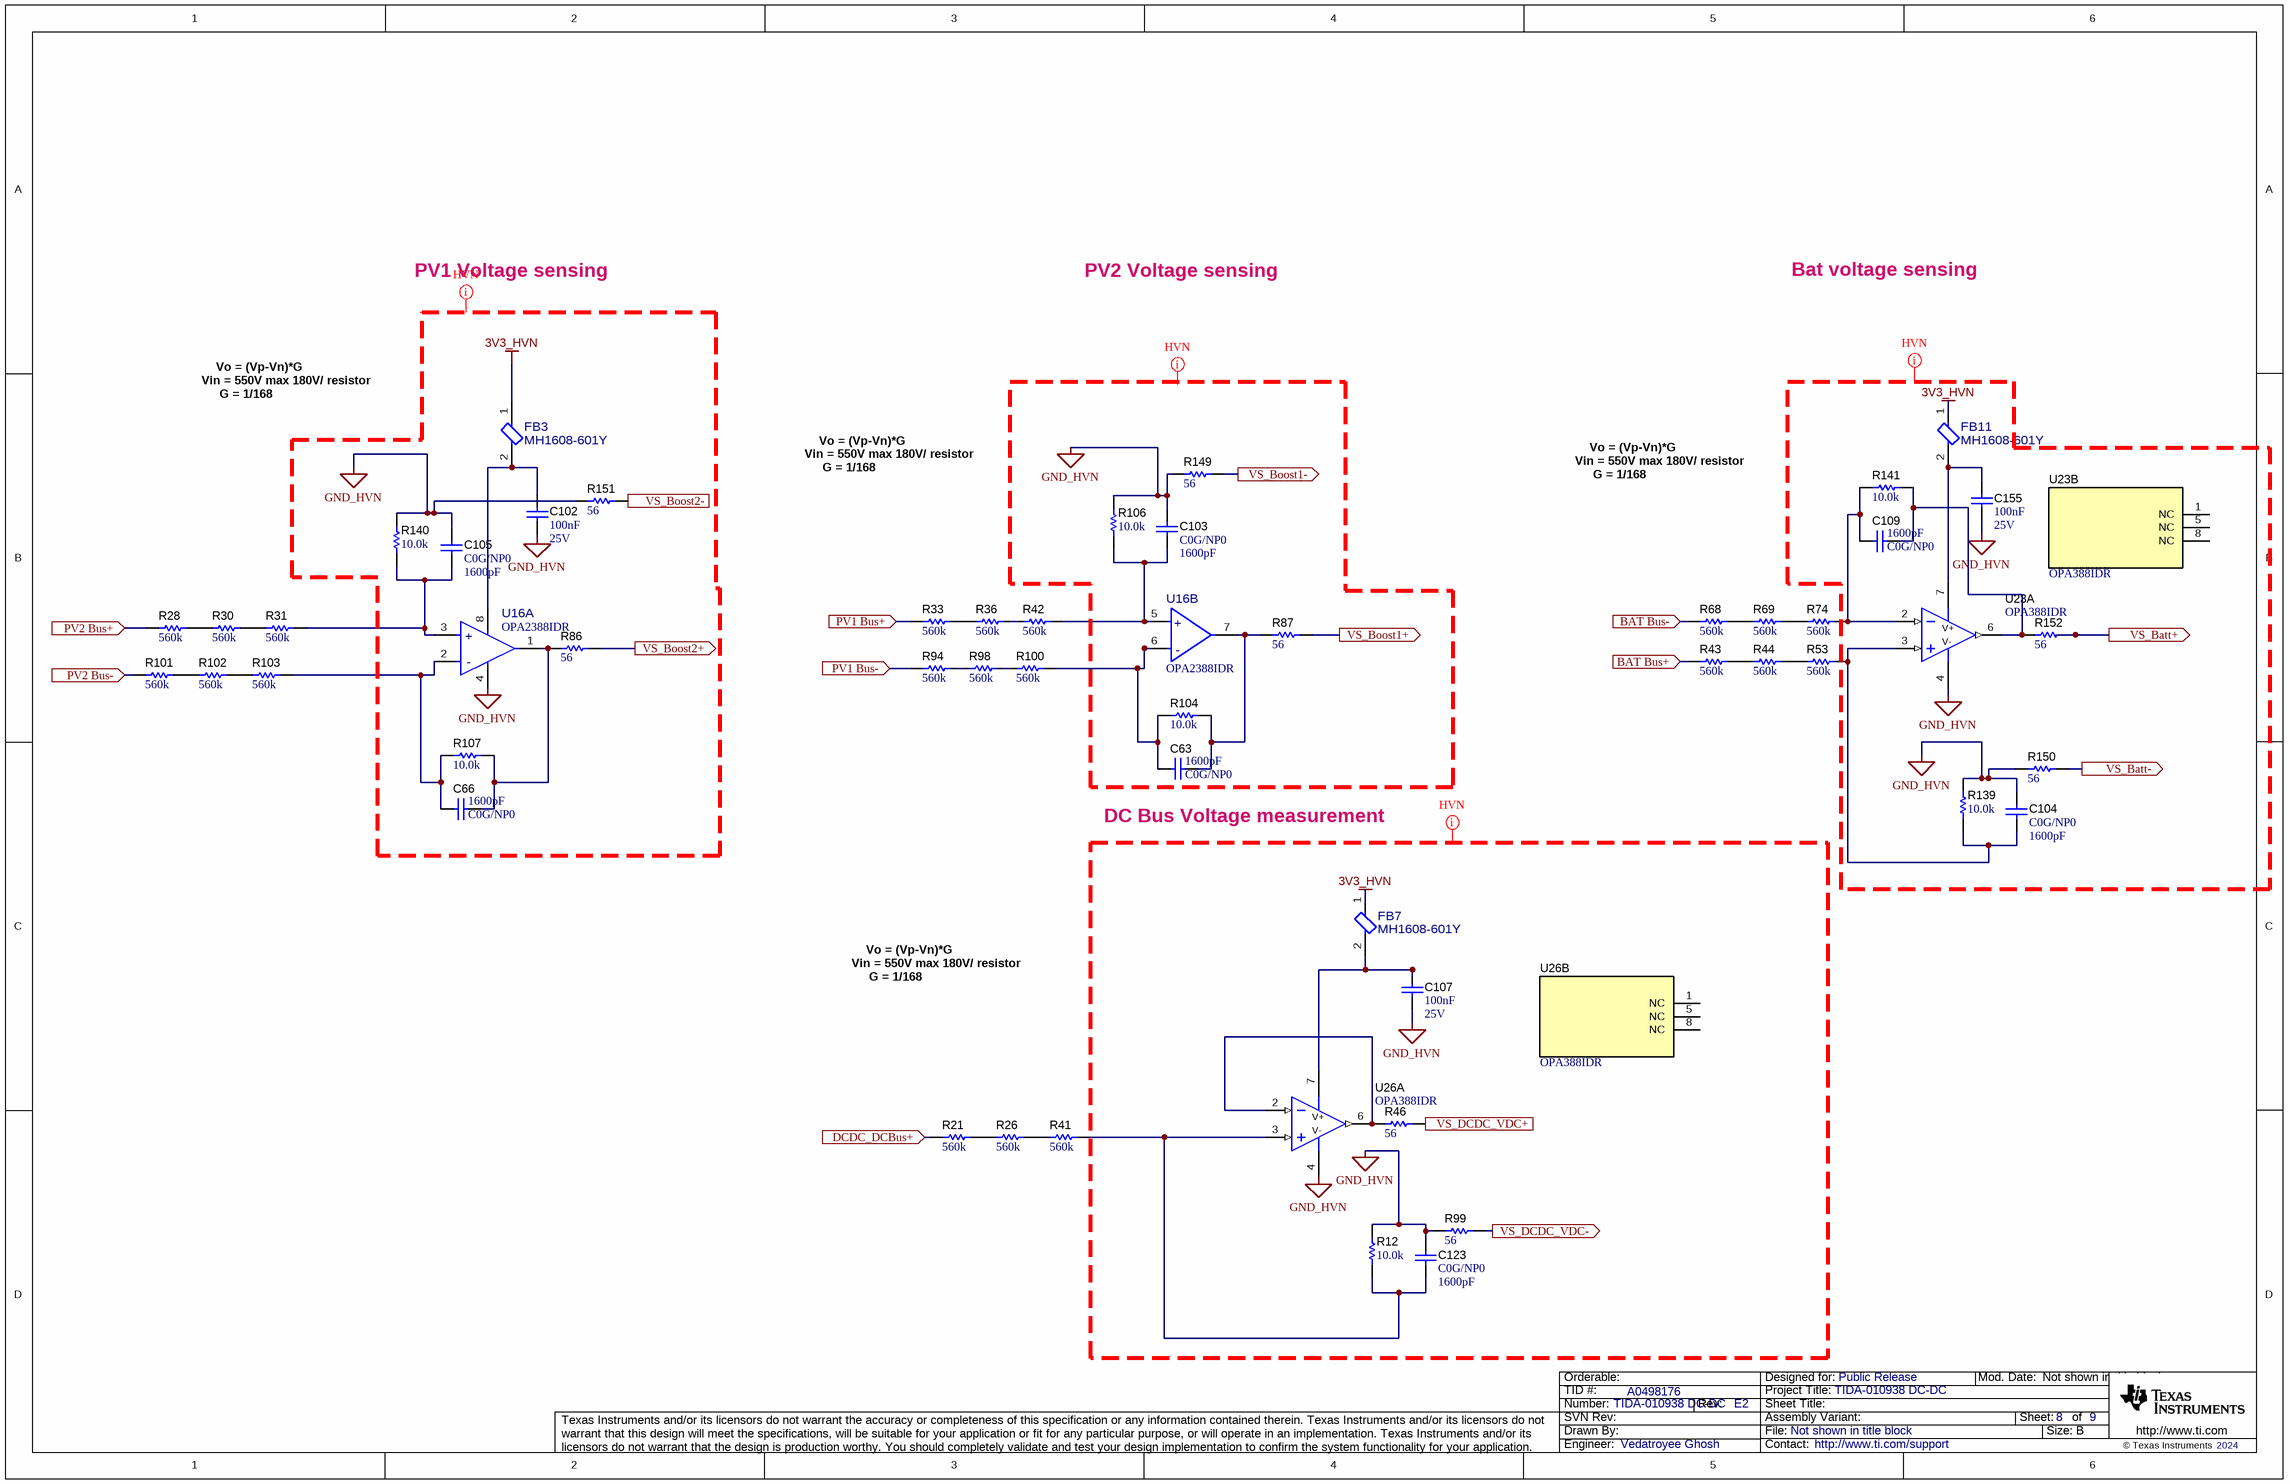
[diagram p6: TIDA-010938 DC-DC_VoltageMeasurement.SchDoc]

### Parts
C63  TempCo: C0G/NP0  ValueDisplayed: 1600pF  [0603]  (hidden comment: GRM1885C1H162JA01D)
C66  TempCo: C0G/NP0  ValueDisplayed: 1600pF  [0603]  (hidden comment: GRM1885C1H162JA01D)
C102  Cap_F: 100nF  VDC_V: 25V  [0603]  (hidden comment: 06033C104JAT2A)
C103  TempCo: C0G/NP0  ValueDisplayed: 1600pF  [0603]  (hidden comment: GRM1885C1H162JA01D)
C104  TempCo: C0G/NP0  ValueDisplayed: 1600pF  [0603]  (hidden comment: GRM1885C1H162JA01D)
C105  TempCo: C0G/NP0  ValueDisplayed: 1600pF  [0603]  (hidden comment: GRM1885C1H162JA01D)
C107  Cap_F: 100nF  VDC_V: 25V  [0603]  (hidden comment: 06033C104JAT2A)
C109  TempCo: C0G/NP0  ValueDisplayed: 1600pF  [0603]  (hidden comment: GRM1885C1H162JA01D)
C123  TempCo: C0G/NP0  ValueDisplayed: 1600pF  [0603]  (hidden comment: GRM1885C1H162JA01D)
C155  Cap_F: 100nF  VDC_V: 25V  [0603]  (hidden comment: 06033C104JAT2A)
FB3  MH1608-601Y  [FP-MH1608-601Y_0603-MFG]
FB7  MH1608-601Y  [FP-MH1608-601Y_0603-MFG]
FB11  MH1608-601Y  [FP-MH1608-601Y_0603-MFG]
R12  ValueDisplayed: 10.0k  [0603]  (hidden comment: RG1608P-103-B-T5)
R21  ValueDisplayed: 560k  [TNPV1206]  (hidden comment: TNPV1206560KBEEN)
R26  ValueDisplayed: 560k  [TNPV1206]  (hidden comment: TNPV1206560KBEEN)
R28  ValueDisplayed: 560k  [TNPV1206]  (hidden comment: TNPV1206560KBEEN)
R30  ValueDisplayed: 560k  [TNPV1206]  (hidden comment: TNPV1206560KBEEN)
R31  ValueDisplayed: 560k  [TNPV1206]  (hidden comment: TNPV1206560KBEEN)
R33  ValueDisplayed: 560k  [TNPV1206]  (hidden comment: TNPV1206560KBEEN)
R36  ValueDisplayed: 560k  [TNPV1206]  (hidden comment: TNPV1206560KBEEN)
R41  ValueDisplayed: 560k  [TNPV1206]  (hidden comment: TNPV1206560KBEEN)
R42  ValueDisplayed: 560k  [TNPV1206]  (hidden comment: TNPV1206560KBEEN)
R43  ValueDisplayed: 560k  [TNPV1206]  (hidden comment: TNPV1206560KBEEN)
R44  ValueDisplayed: 560k  [TNPV1206]  (hidden comment: TNPV1206560KBEEN)
R46  ValueDisplayed: 56  [0603]  (hidden comment: RG1608P-560-B-T5)
R53  ValueDisplayed: 560k  [TNPV1206]  (hidden comment: TNPV1206560KBEEN)
R68  ValueDisplayed: 560k  [TNPV1206]  (hidden comment: TNPV1206560KBEEN)
R69  ValueDisplayed: 560k  [TNPV1206]  (hidden comment: TNPV1206560KBEEN)
R74  ValueDisplayed: 560k  [TNPV1206]  (hidden comment: TNPV1206560KBEEN)
R86  ValueDisplayed: 56  [0603]  (hidden comment: RG1608P-560-B-T5)
R87  ValueDisplayed: 56  [0603]  (hidden comment: RG1608P-560-B-T5)
R94  ValueDisplayed: 560k  [TNPV1206]  (hidden comment: TNPV1206560KBEEN)
R98  ValueDisplayed: 560k  [TNPV1206]  (hidden comment: TNPV1206560KBEEN)
R99  ValueDisplayed: 56  [0603]  (hidden comment: RG1608P-560-B-T5)
R100  ValueDisplayed: 560k  [TNPV1206]  (hidden comment: TNPV1206560KBEEN)
R101  ValueDisplayed: 560k  [TNPV1206]  (hidden comment: TNPV1206560KBEEN)
R102  ValueDisplayed: 560k  [TNPV1206]  (hidden comment: TNPV1206560KBEEN)
R103  ValueDisplayed: 560k  [TNPV1206]  (hidden comment: TNPV1206560KBEEN)
R104  ValueDisplayed: 10.0k  [0603]  (hidden comment: RG1608P-103-B-T5)
R106  ValueDisplayed: 10.0k  [0603]  (hidden comment: RG1608P-103-B-T5)
R107  ValueDisplayed: 10.0k  [0603]  (hidden comment: RG1608P-103-B-T5)
R139  ValueDisplayed: 10.0k  [0603]  (hidden comment: RG1608P-103-B-T5)
R140  ValueDisplayed: 10.0k  [0603]  (hidden comment: RG1608P-103-B-T5)
R141  ValueDisplayed: 10.0k  [0603]  (hidden comment: RG1608P-103-B-T5)
R149  ValueDisplayed: 56  [0603]  (hidden comment: RG1608P-560-B-T5)
R150  ValueDisplayed: 56  [0603]  (hidden comment: RG1608P-560-B-T5)
R151  ValueDisplayed: 56  [0603]  (hidden comment: RG1608P-560-B-T5)
R152  ValueDisplayed: 56  [0603]  (hidden comment: RG1608P-560-B-T5)
U16  OPA2388IDR  [D0008A-MFG]  (parts A,B of 2)
U23  OPA388IDR  [D0008A_L]  (parts A,B of 2)
U26  OPA388IDR  [D0008A_L]  (parts A,B of 2)

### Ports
BAT Bus+ (in), BAT Bus- (in), DCDC_DCBus+ (in), PV1 Bus+ (in), PV1 Bus- (in), PV2 Bus+ (in), PV2 Bus- (in), VS_Batt+ (out), VS_Batt- (out), VS_Boost1+ (out), VS_Boost1- (out), VS_Boost2+ (out), VS_Boost2- (out), VS_DCDC_VDC+ (out), VS_DCDC_VDC- (out)

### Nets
3V3_HVN: FB3.1 FB7.1 FB11.1
GND_HVN: C102.1 C103.1 C104.1 C105.1 C107.1 C123.1 C155.1 R12.2 R99.1 R106.2 R139.2 R140.1 R149.1 R150.1 R151.1 U16.4(V-) U23.4(V-) U26.4(V-)  [project net DC_Bus-]
BAT Bus+: R43.1 ; port BAT Bus+
BAT Bus-: R68.1 ; port BAT Bus-
Boost1_IN-: R94.1 ; port PV1 Bus-
Boost2_IN-: R101.1 ; port PV2 Bus-
DCDC_DCBus+: R21.1 ; port DCDC_DCBus+
PV1 Bus+: R33.1 ; port PV1 Bus+
PV2 Bus+: R28.1 ; port PV2 Bus+
VS_Batt+: R152.2 ; port VS_Batt+
VS_Batt-: R150.2 ; port VS_Batt-
VS_Boost1+: R87.2 ; port VS_Boost1+
VS_Boost1-: R149.2 ; port VS_Boost1-
VS_Boost2+: R86.2 ; port VS_Boost2+
VS_Boost2-: R151.2 ; port VS_Boost2-
VS_DCDC_VDC+: R46.2 ; port VS_DCDC_VDC+
VS_DCDC_VDC-: R99.2 ; port VS_DCDC_VDC-
NetC63_1: C63.1 R100.2 R104.1 U16.6(-IN_B)
NetC63_2: C63.2 R87.1 R104.2 U16.7(OUT_B)
NetC66_1: C66.1 R103.2 R107.1 U16.2(-IN_A)
NetC66_2: C66.2 R86.1 R107.2 U16.1(OUT_A)
NetC102_2: C102.2 FB3.2 U16.8(V+)
NetC103_2: C103.2 R42.2 R106.1 U16.5(+IN_B)
NetC104_2: C104.2 R53.2 R139.1 U23.3(IN+)
NetC105_2: C105.2 R31.2 R140.2 U16.3(+IN_A)
NetC107_2: C107.2 FB7.2 U26.7(V+)
NetC109_1: C109.1 R74.2 R141.1 U23.2(IN-)
NetC109_2: C109.2 R141.2 R152.1 U23.6(OUT)
NetC123_2: C123.2 R12.1 R41.2 U26.3(IN+)
NetC155_2: C155.2 FB11.2 U23.7(V+)
NetR21_2: R21.2 R26.1
NetR26_2: R26.2 R41.1
NetR28_2: R28.2 R30.1
NetR30_2: R30.2 R31.1
NetR33_2: R33.2 R36.1
NetR36_2: R36.2 R42.1
NetR43_2: R43.2 R44.1
NetR44_2: R44.2 R53.1
NetR46_1: R46.1 U26.2(IN-) U26.6(OUT)
NetR68_2: R68.2 R69.1
NetR69_2: R69.2 R74.1
NetR94_2: R94.2 R98.1
NetR98_2: R98.2 R100.1
NetR101_2: R101.2 R102.1
NetR102_2: R102.2 R103.1

Not connected (* = marked no-connect by the designer): U23 1(NC) 5(NC) 8(NC); U26 1(NC) 5(NC) 8(NC)

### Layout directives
net class HVN: 3V3_HVN, GND_HVN

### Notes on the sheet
- PV1 Voltage sensing
- PV2 Voltage sensing
- Bat voltage sensing
- Vo = (Vp-Vn)*G
- G = 1/168
- Vin = 550V max 180V/ resistor
- (near C63) DC Bus Voltage measurement

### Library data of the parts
C63 C66 C103-C105 C109 C123 = CMP-0007189-4: CAP, CERM, 1600 pF, 50 V, +/- 5%, C0G/NP0, 0603; Manufacturer: MuRata; TaMin_C: -55°C; Polarized: N; SizeAreaWB_mm2: 4.68; Value1: Unknown; U/M: EA; Value: 1600pF; TaMax_C: 125°C; SizeZ_mm: 1; SizeX_mm: 1.6; SizeY_mm: 0.8; Value2: 50V; SizeArea_mm2: 1.28; Cap_F: 1.6nF; AEC Category: Q200
C102 C107 C155 = CMP-0006752-5: as C36 on sheet TIDA-010938 bidirectional DC-DC_Interleaved1
FB3 FB7 FB11 = CMP-0037505-1: as FB4 on sheet TIDA-010938 bidirectional DC-DC_Interleaved1
R12 R104 R106 R107 R139-R141 = CMP-0023404-3: as R39 on sheet TIDA-010938 bidirectional DC-DC_Interleaved1
R21 R26 R28 R30 R31 R33 R36 R41-R44 R53 R68 R69 R74 R94 R98 R100-R103 = CMP-0018815-2: RES, 560 k, 0.1%, 1 W, 1206; Manufacturer: Vishay Draloric; Power_W: 1W; TempCo: 25 ppm/C; U/M: EA; Value: 560k; SizeX_mm: 3.2; SizeY_mm: 1.6; SizeZ_mm: 0.65; SizeArea_mm2: 5.12; AEC Qualified: N; VDC_V: 700V; AEC Category: Q200
R46 R86 R87 R99 R149-R152 = CMP-0023572-3: as R3-R5 on sheet TIDA-010938 bidirectional DC-DC_Interleaved1
U16 = CMP-0097119-1: Precision, Zero-Drift, Zero-Crossover, True Rail-to-Rail, Input/Output Operational Amplifiers; Manufacturer: Texas Instruments; TJmax_C: +150°C; TaMin_C: -55°C; AEC Qualified: No; Max Dual Supply Voltage: 2.75V; Min Dual Supply Voltage: 1.25V; Input Offset Voltage: 0.00025mV; Output Current Per Channel: 30-60mA; Standoff Height: 0.11mm; Number Of Channels: 2; Min Supply Voltage: 2.5V; Input Bias Current: 0.00003uA; Nominal Supply Current: 1.7-1.9mA; Voltage Gain: 126-148dB; Bandwidth: 10MHz; SizeZ_mm: 1.75mm; Max Supply Voltage: 5.5V; Response Time: 0.75-2us
U23 U26 = CMP-0075798-1: Precision, Zero-Drift, Zero-Crossover, True Rail-to-Rail Input/Output, Operational Amplifier, D0008A (SOIC-8); Manufacturer: Texas Instruments; SizeAreaWB_mm2: 56.58; SizeArea_mm2: 30.38; SizeZ_mm: 1.75; SizeY_mm: 6.2; U/M: EA; CompType: IC; SizeX_mm: 4.9

## Sheet TIDA-010938 DC-DC_Data conditionning.SchDoc
size 431 x 279 mm; Date: Not shown in title block; ApprovedBy: Not shown in title block; CheckedBy: Not shown in title block; Author: Not shown in title block; CompanyName: Not shown in title block; Engineer: Not shown in title block; Organization: Not shown in title block; Address1: Not shown in title block; Address2: Not shown in title block; Address3: Not shown in title block; Address4: Not shown in title block; DocumentNumber: 1; Revision: Use project parameter SCH_Rev; SheetNumber: 7; SheetTotal: 9; PageSetup: Record=PageOptions¦CenterHorizontal=True¦CenterVertical=True¦PrintScale=1.00¦XCorrection=1.00¦YCorrection=1.00¦PrintKind=0¦BorderSize=5000000¦LeftOffset=0¦BottomOffset=0¦Orientation=2¦PaperLength=1000¦PaperWidth=1000¦Scale=100¦PaperSource=15¦PrintQuality=600¦MediaType=1¦DitherType=10¦PaperKind=Letter¦PrintScaleMode=1
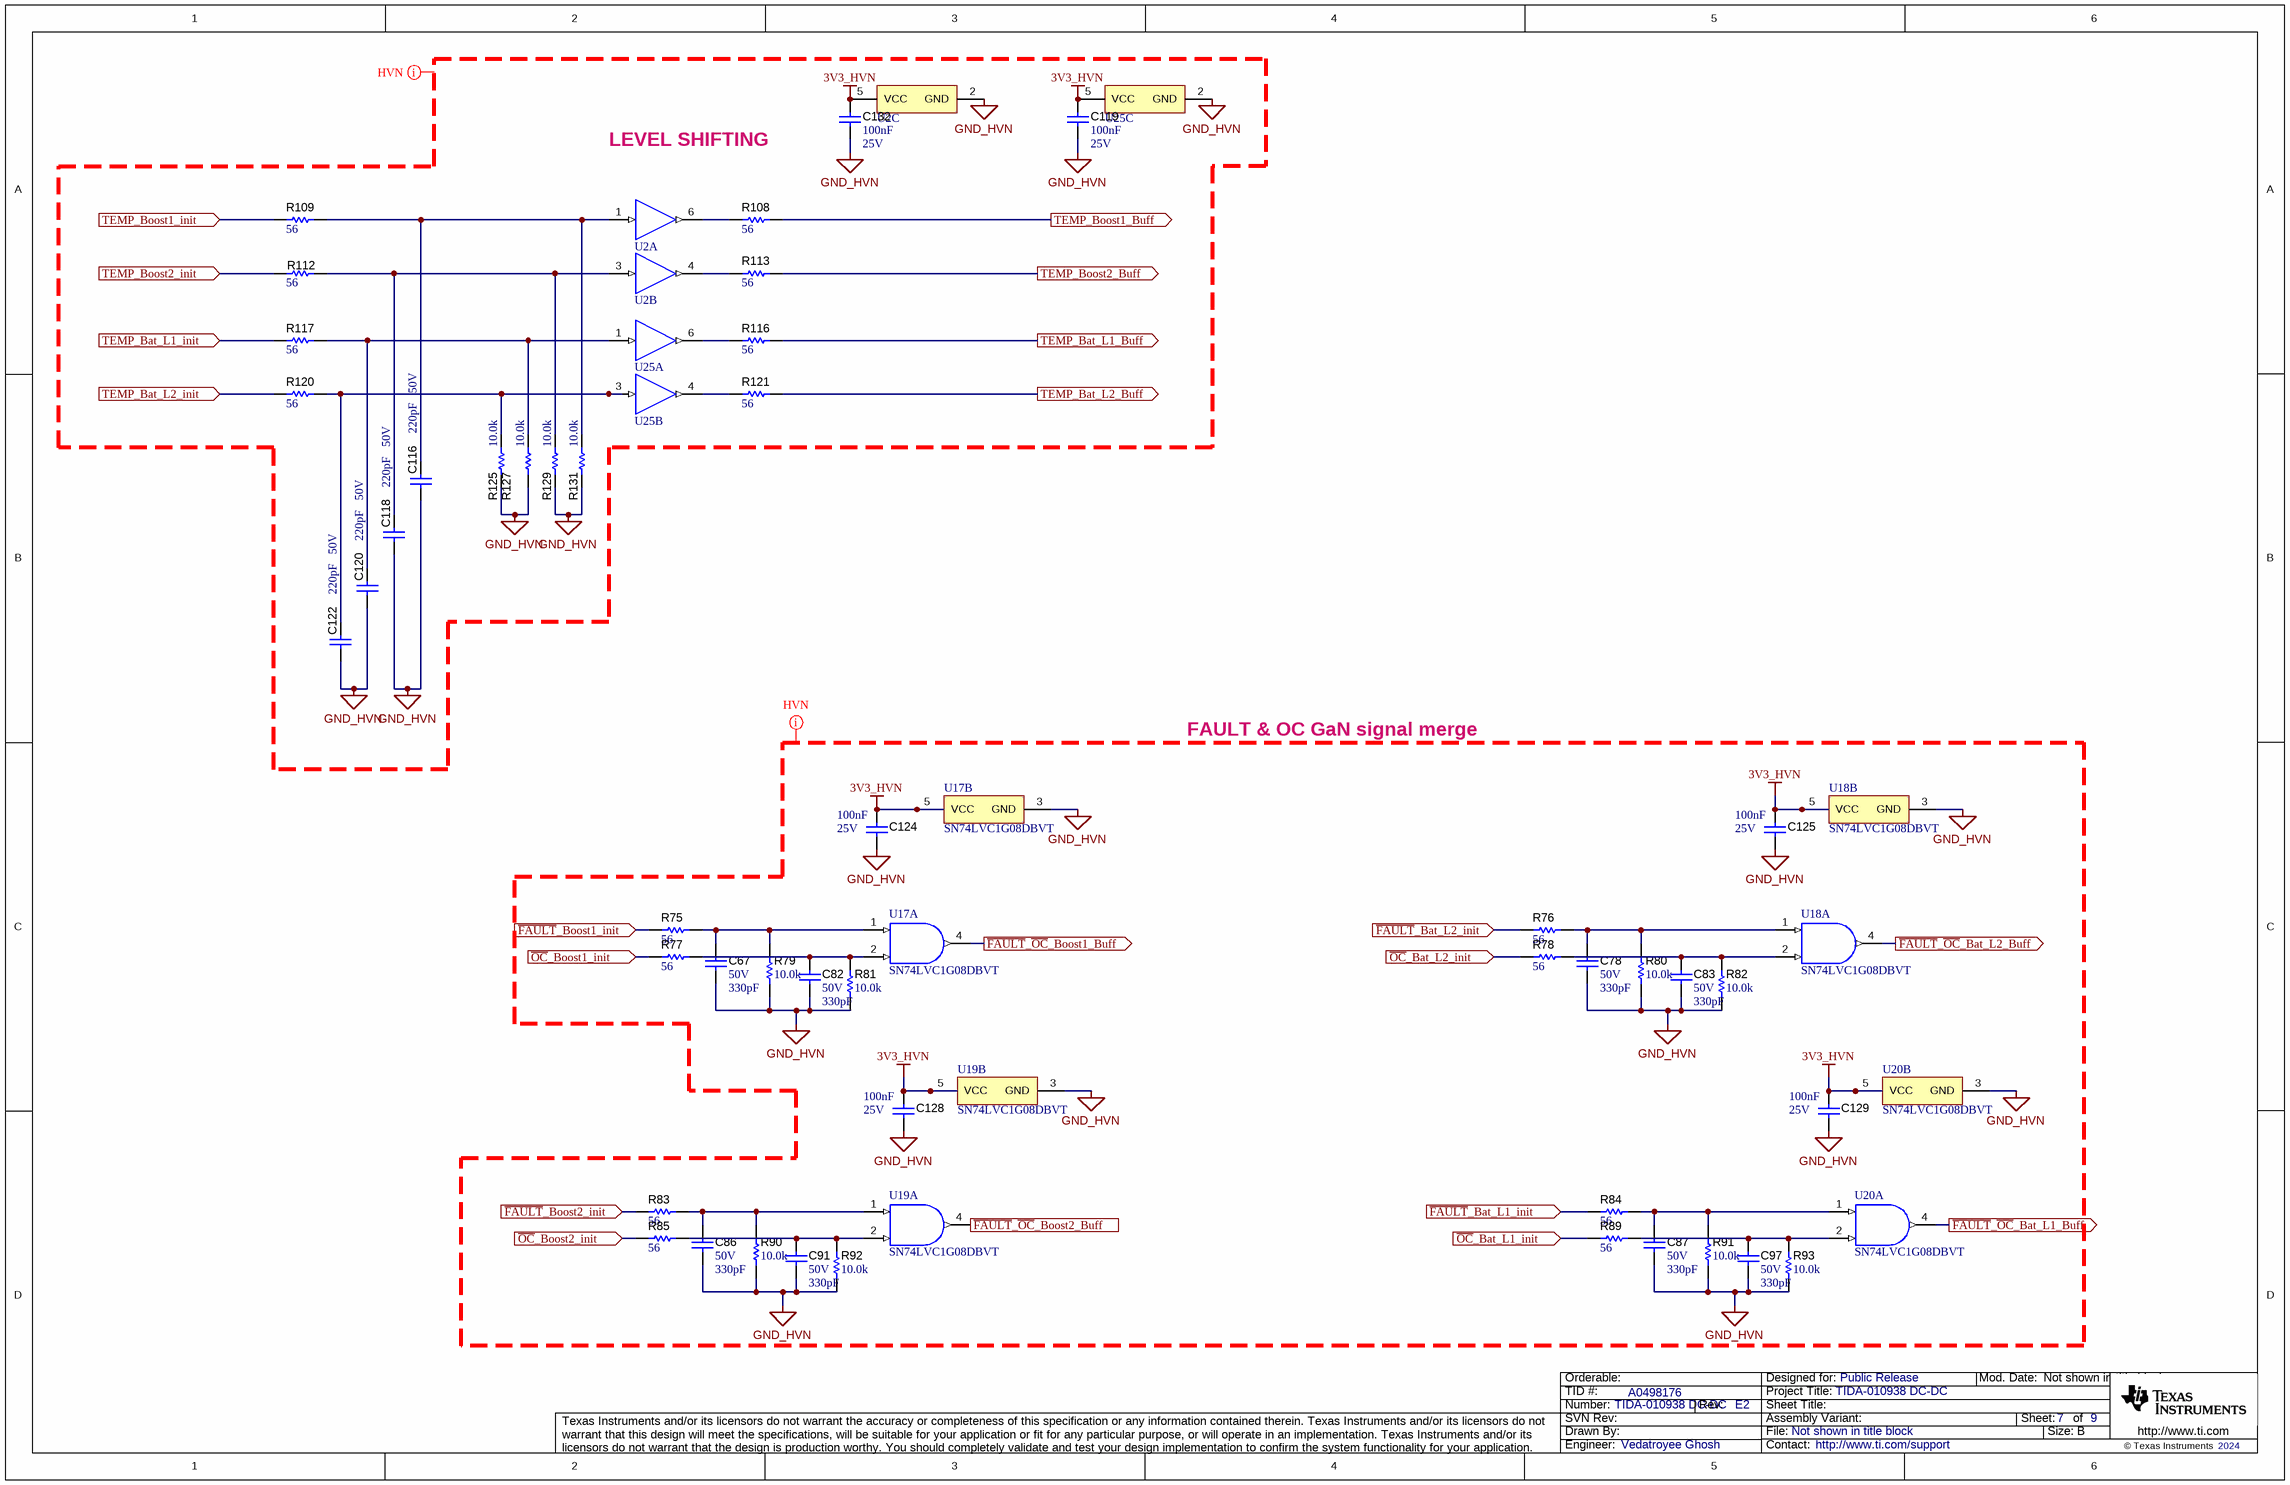
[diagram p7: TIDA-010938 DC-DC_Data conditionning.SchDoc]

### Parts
C67  VDC_V: 50V  ValueDisplayed: 330pF  [0603]  (hidden comment: C0603C331J5GACTU)
C78  VDC_V: 50V  ValueDisplayed: 330pF  [0603]  (hidden comment: C0603C331J5GACTU)
C82  VDC_V: 50V  ValueDisplayed: 330pF  [0603]  (hidden comment: C0603C331J5GACTU)
C83  VDC_V: 50V  ValueDisplayed: 330pF  [0603]  (hidden comment: C0603C331J5GACTU)
C86  VDC_V: 50V  ValueDisplayed: 330pF  [0603]  (hidden comment: C0603C331J5GACTU)
C87  VDC_V: 50V  ValueDisplayed: 330pF  [0603]  (hidden comment: C0603C331J5GACTU)
C91  VDC_V: 50V  ValueDisplayed: 330pF  [0603]  (hidden comment: C0603C331J5GACTU)
C97  VDC_V: 50V  ValueDisplayed: 330pF  [0603]  (hidden comment: C0603C331J5GACTU)
C116  Cap_F: 220pF  VDC_V: 50V  [0603]  (hidden comment: GRM188R71H221KA01D)
C118  Cap_F: 220pF  VDC_V: 50V  [0603]  (hidden comment: GRM188R71H221KA01D)
C119  Cap_F: 100nF  VDC_V: 25V  [0603]  (hidden comment: 06033C104JAT2A)
C120  Cap_F: 220pF  VDC_V: 50V  [0603]  (hidden comment: GRM188R71H221KA01D)
C122  Cap_F: 220pF  VDC_V: 50V  [0603]  (hidden comment: GRM188R71H221KA01D)
C124  Cap_F: 100nF  VDC_V: 25V  [0603]  (hidden comment: 06033C104JAT2A)
C125  Cap_F: 100nF  VDC_V: 25V  [0603]  (hidden comment: 06033C104JAT2A)
C128  Cap_F: 100nF  VDC_V: 25V  [0603]  (hidden comment: 06033C104JAT2A)
C129  Cap_F: 100nF  VDC_V: 25V  [0603]  (hidden comment: 06033C104JAT2A)
C132  Cap_F: 100nF  VDC_V: 25V  [0603]  (hidden comment: 06033C104JAT2A)
R75  ValueDisplayed: 56  [0603]  (hidden comment: RG1608P-560-B-T5)
R76  ValueDisplayed: 56  [0603]  (hidden comment: RG1608P-560-B-T5)
R77  ValueDisplayed: 56  [0603]  (hidden comment: RG1608P-560-B-T5)
R78  ValueDisplayed: 56  [0603]  (hidden comment: RG1608P-560-B-T5)
R79  ValueDisplayed: 10.0k  [0603]  (hidden comment: RG1608P-103-B-T5)
R80  ValueDisplayed: 10.0k  [0603]  (hidden comment: RG1608P-103-B-T5)
R81  ValueDisplayed: 10.0k  [0603]  (hidden comment: RG1608P-103-B-T5)
R82  ValueDisplayed: 10.0k  [0603]  (hidden comment: RG1608P-103-B-T5)
R83  ValueDisplayed: 56  [0603]  (hidden comment: RG1608P-560-B-T5)
R84  ValueDisplayed: 56  [0603]  (hidden comment: RG1608P-560-B-T5)
R85  ValueDisplayed: 56  [0603]  (hidden comment: RG1608P-560-B-T5)
R89  ValueDisplayed: 56  [0603]  (hidden comment: RG1608P-560-B-T5)
R90  ValueDisplayed: 10.0k  [0603]  (hidden comment: RG1608P-103-B-T5)
R91  ValueDisplayed: 10.0k  [0603]  (hidden comment: RG1608P-103-B-T5)
R92  ValueDisplayed: 10.0k  [0603]  (hidden comment: RG1608P-103-B-T5)
R93  ValueDisplayed: 10.0k  [0603]  (hidden comment: RG1608P-103-B-T5)
R108  ValueDisplayed: 56  [0603]  (hidden comment: RG1608P-560-B-T5)
R109  ValueDisplayed: 56  [0603]  (hidden comment: RG1608P-560-B-T5)
R112  ValueDisplayed: 56  [0603]  (hidden comment: RG1608P-560-B-T5)
R113  ValueDisplayed: 56  [0603]  (hidden comment: RG1608P-560-B-T5)
R116  ValueDisplayed: 56  [0603]  (hidden comment: RG1608P-560-B-T5)
R117  ValueDisplayed: 56  [0603]  (hidden comment: RG1608P-560-B-T5)
R120  ValueDisplayed: 56  [0603]  (hidden comment: RG1608P-560-B-T5)
R121  ValueDisplayed: 56  [0603]  (hidden comment: RG1608P-560-B-T5)
R125  ValueDisplayed: 10.0k  [0603]  (hidden comment: RG1608P-103-B-T5)
R127  ValueDisplayed: 10.0k  [0603]  (hidden comment: RG1608P-103-B-T5)
R129  ValueDisplayed: 10.0k  [0603]  (hidden comment: RG1608P-103-B-T5)
R131  ValueDisplayed: 10.0k  [0603]  (hidden comment: RG1608P-103-B-T5)
U2  SN74LVC2G34DBVR  [DBV0006A_N]  (value not drawn)  (parts A,B,C of 3)
U17  SN74LVC1G08DBVT  [DBV0005A_N]  (parts A,B of 2)
U18  SN74LVC1G08DBVT  [DBV0005A_N]  (parts A,B of 2)
U19  SN74LVC1G08DBVT  [DBV0005A_N]  (parts A,B of 2)
U20  SN74LVC1G08DBVT  [DBV0005A_N]  (parts A,B of 2)
U25  SN74LVC2G34DBVR  [DBV0006A_N]  (value not drawn)  (parts A,B,C of 3)

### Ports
TEMP_Bat_L1_Buff (out), TEMP_Bat_L1_init (in), TEMP_Bat_L2_Buff (out), TEMP_Bat_L2_init (in), TEMP_Boost1_Buff (out), TEMP_Boost1_init (in), TEMP_Boost2_Buff (out), TEMP_Boost2_init (in), ~{FAULT}_Bat_L1_init (in), ~{FAULT}_Bat_L2_init (in), ~{FAULT}_Boost1_init (in), ~{FAULT}_Boost2_init (in), ~{FAULT}_~{OC}_Bat_L1_Buff (out), ~{FAULT}_~{OC}_Bat_L2_Buff (out), ~{FAULT}_~{OC}_Boost1_Buff (out), ~{FAULT}_~{OC}_Boost2_Buff (out), ~{OC}_Bat_L1_init (in), ~{OC}_Bat_L2_init (in), ~{OC}_Boost1_init (in), ~{OC}_Boost2_init (in)

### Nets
3V3_HVN: C119.2 C124.1 C125.1 C128.1 C129.1 C132.2 U2.5(VCC) U17.5(VCC) U18.5(VCC) U19.5(VCC) U20.5(VCC) U25.5(VCC)
GND_HVN: C67.2 C78.2 C82.2 C83.2 C86.2 C87.2 C91.2 C97.2 C116.1 C118.1 C119.1 C120.1 C122.1 C124.2 C125.2 C128.2 C129.2 C132.1 R79.1 R80.1 R81.1 R82.1 R90.1 R91.1 R92.1 R93.1 R125.1 R127.1 R129.1 R131.1 U2.2(GND) U17.3(GND) U18.3(GND) U19.3(GND) U20.3(GND) U25.2(GND)  [project net DC_Bus-]
~{FAULT}_Bat_L1_init: R84.1 ; port ~{FAULT}_Bat_L1_init
~{FAULT}_Bat_L2_init: R76.1 ; port ~{FAULT}_Bat_L2_init
~{FAULT}_Boost1_init: R75.1 ; port ~{FAULT}_Boost1_init
~{FAULT}_Boost2_init: R83.1 ; port ~{FAULT}_Boost2_init
~{FAULT}_~{OC}_Bat_L1_Buff: U20.4(Y) ; port ~{FAULT}_~{OC}_Bat_L1_Buff
~{FAULT}_~{OC}_Bat_L2_Buff: U18.4(Y) ; port ~{FAULT}_~{OC}_Bat_L2_Buff
~{FAULT}_~{OC}_Boost1_Buff: U17.4(Y) ; port ~{FAULT}_~{OC}_Boost1_Buff
~{FAULT}_~{OC}_Boost2_Buff: U19.4(Y) ; port ~{FAULT}_~{OC}_Boost2_Buff
~{OC}_Bat_L1_init: R89.1 ; port ~{OC}_Bat_L1_init
~{OC}_Bat_L2_init: R78.1 ; port ~{OC}_Bat_L2_init
~{OC}_Boost1_init: R77.1 ; port ~{OC}_Boost1_init
~{OC}_Boost2_init: R85.1 ; port ~{OC}_Boost2_init
TEMP_Bat_L1_Buff: R116.2 ; port TEMP_Bat_L1_Buff
TEMP_Bat_L1_init: R117.1 ; port TEMP_Bat_L1_init
TEMP_Bat_L2_Buff: R121.2 ; port TEMP_Bat_L2_Buff
TEMP_Bat_L2_init: R120.1 ; port TEMP_Bat_L2_init
TEMP_Boost1_Buff: R108.2 ; port TEMP_Boost1_Buff
TEMP_Boost1_init: R109.1 ; port TEMP_Boost1_init
TEMP_Boost2_Buff: R113.2 ; port TEMP_Boost2_Buff
TEMP_Boost2_init: R112.1 ; port TEMP_Boost2_init
NetC67_1: C67.1 R75.2 R79.2 U17.1(A)
NetC78_1: C78.1 R76.2 R80.2 U18.1(A)
NetC82_1: C82.1 R77.2 R81.2 U17.2(B)
NetC83_1: C83.1 R78.2 R82.2 U18.2(B)
NetC86_1: C86.1 R83.2 R90.2 U19.1(A)
NetC87_1: C87.1 R84.2 R91.2 U20.1(A)
NetC91_1: C91.1 R85.2 R92.2 U19.2(B)
NetC97_1: C97.1 R89.2 R93.2 U20.2(B)
NetC116_2: C116.2 R109.2 R131.2 U2.1(1A)
NetC118_2: C118.2 R112.2 R129.2 U2.3(2A)
NetC120_2: C120.2 R117.2 R127.2 U25.1(1A)
NetC122_2: C122.2 R120.2 R125.2 U25.3(2A)
NetR108_1: R108.1 U2.6(1Y)
NetR113_1: R113.1 U2.4(2Y)
NetR116_1: R116.1 U25.6(1Y)
NetR121_1: R121.1 U25.4(2Y)

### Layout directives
net class HVN: 3V3_HVN, GND_HVN

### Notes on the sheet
- LEVEL SHIFTING
- FAULT & OC GaN signal merge

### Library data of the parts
C67 C78 C82 C83 C86 C87 C91 C97 = CMP-0006920-4: CAP, CERM, 330 pF, 50 V, +/- 5%, C0G/NP0, 0603; Manufacturer: Kemet; TaMin_C: -55°C; Polarized: N; SizeAreaWB_mm2: 4.68; Value1: Unknown; U/M: EA; Value: 330pF; TaMax_C: 125°C; SizeZ_mm: 1; SizeX_mm: 1.6; SizeY_mm: 0.8; SizeArea_mm2: 1.28; AEC Category: Q200
C116 C118 C120 C122 = CMP-0007442-5: as C11 on sheet TIDA-010938 bidirectional DC-DC_Interleaved1
C119 C124 C125 C128 C129 C132 = CMP-0006752-5: as C36 on sheet TIDA-010938 bidirectional DC-DC_Interleaved1
R75-R78 R83-R85 R89 R108 R109 R112 R113 R116 R117 R120 R121 = CMP-0023572-3: as R3-R5 on sheet TIDA-010938 bidirectional DC-DC_Interleaved1
R79-R82 R90-R93 R125 R127 R129 R131 = CMP-0023404-3: as R39 on sheet TIDA-010938 bidirectional DC-DC_Interleaved1
U2 U25 = CMP-0051910-1: Dual Buffer Gate, DBV0006A, LARGE T&R; Manufacturer: Texas Instruments; Logic: True; F @ Nom Voltage(Max)(Mhz): 150; Output Type: CMOS; Output Drive (IOL/IOH)(Max)(mA): 32/-32; Voltage(Nom)(V): 1.8,2.5,3.3,5; 3-State Output: No; VCC(Max)(V): 5.5; ICC @ Nom Voltage(Max)(mA): 0.01; Technology Family: LVC; Input Type: CMOS/TTL; VCC(Min)(V): 1.65; Bits(#): 2; tpd @ Nom Voltage(Max)(ns): 8.6,4.4,4.1,3.2; Rating: Catalog; Sub-Family: Non-Inverting Buffer/Driver
U17-U20 = CMP-0051571-2: as U8 on sheet TIDA-010938 bidirectional DC-DC_Interleaved1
